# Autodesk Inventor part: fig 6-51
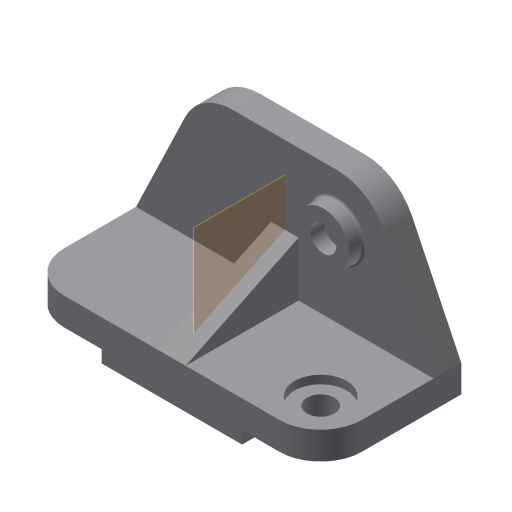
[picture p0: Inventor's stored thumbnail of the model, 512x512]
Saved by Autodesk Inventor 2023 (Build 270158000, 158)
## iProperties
Created: 2001-12
Part Number: fig 6-51
Document SubType Name: Modeling
Designer: Renu Muthoo
Density: 1 g/cm^3
Material: Generic
Appearance: Default
Control State: 0
Master: False
Checked Out: False
Shininess: 77.0
Length Units: 11269
Angle Units: 11279
Time Units: 11290
Mass Units: 11283
Length Display Precision: 3
Angle Display Precision: 2
Density: 0.0
Volumn: 0.0
Area: 0.0
PropertySet Name: Model Information
Author: Renu Muthoo
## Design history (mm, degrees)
node "Sketch1"
sketch "Sketch2"
  geometry: L1 (-67.219, 19.116)-(148.781, 19.116); L2 (148.781, 19.116)-(148.781, -0.884); L3 (-67.219, -0.884)-(-67.219, 19.116); L4 (-10.219, -0.884)-(-10.219, -9.884); L5 (-10.219, -9.884)-(91.781, -9.884); L6 (91.781, -9.884)-(91.781, -0.884); L7 (148.781, -0.884)-(91.781, -0.884); L8 (-10.219, -0.884)-(-67.219, -0.884)
  constraints: 16 end point, 5 parallel, 4 perpendicular, 2 equal length, 1 horizontal
  dimensions: "d0" = 102 distance of L4.end L5.end; "d1" = 57 distance of L4.start L3.start; "d2" = 29 distance between parallel lines of L1 L5; "d3" = 20 distance of L1.end L2.end
extrude "Extrusion1" new body sketch "Sketch2" distance "d4" = 102; taper "d5" = 0 deg
sketch "Sketch3"
  geometry: L1 (67.219, -19.116)-(-148.781, -19.116) reference; L2 (67.219, -19.116)-(31.475, -93.564); L3 (-2.781, -115.116)-(-78.781, -115.116); L4 (-113.038, -93.564)-(-148.781, -19.116); A1 r 38 centre (-2.781, -77.116) between (-2.781, -115.116) and (31.475, -93.564); A2 r 38 centre (-78.781, -77.116) between (-113.038, -93.564) and (-78.781, -115.116)
  constraints: 6 end point, 4 point on circle, 4 tangent, 2 centre point, 1 equal length, 1 equal radius, 1 parallel
  dimensions: "d6" = 96 distance between parallel lines of L3 L1; "d7" = 38 radius of A1; "d8" = 76 distance of A2.centre A1.centre
extrude "Extrusion2" join sketch "Sketch3" distance "d9" = 20; taper "d10" = 0 deg
fillet "Fillet1" dims "d11" = 30
workplane "Work Plane1"
sketch "Sketch5"
  geometry: A1 r 30 centre (-30, 0) between (-30, -30) and (0, 0) reference; 1 further point
  constraints: 1 coincident
hole "Hole1" sketch "Sketch5" at (-30, 0) diameter "d16" = 20; stored, may be unused: countersink angle "d20" = 82 deg, drill point angle "d22" = 118 deg; dims "d17" = 6, "d18" = 38, "d19" = 6, "d21" = 8
sketch "Sketch6"
  geometry: C1 r 19 at (-2.781, 77.116); C2 r 9.5 at (-2.781, 77.116); A1 r 38 centre (-2.781, 77.116) between (31.475, 93.564) and (-2.781, 115.116) reference
  constraints: 2 centre point, 2 coincident
  dimensions: "d23" = 38 diameter of C1; "d24" = 19 diameter of C2
extrude "Extrusion3" join sketch "Sketch6" distance "d25" = 10; taper "d26" = 0 deg
sketch "Sketch7"
  geometry: L1 (0, -82)-(-39.557, 0); L2 (0, -82)-(20, -82) reference; L3 (29, 22.405)-(29, -82); L4 (29, -82)-(0, -82); L5 (0, -82)-(0, 0); L6 (0, 0)-(-90.034, 0); L7 (-90.034, 0)-(-90.034, 22.405); L8 (-90.034, 22.405)-(29, 22.405); L9 (0, 0)-(-74.447, 0) reference
  constraints: 14 end point, 1 collinear, 1 point on line
feature "Rib3" sketch "Sketch7" dims "d35" = 10, "d36" = 20
fillet "Fillet3" dims "d37" = 2
body "Solid1"
other parameters: "d12" = -108
